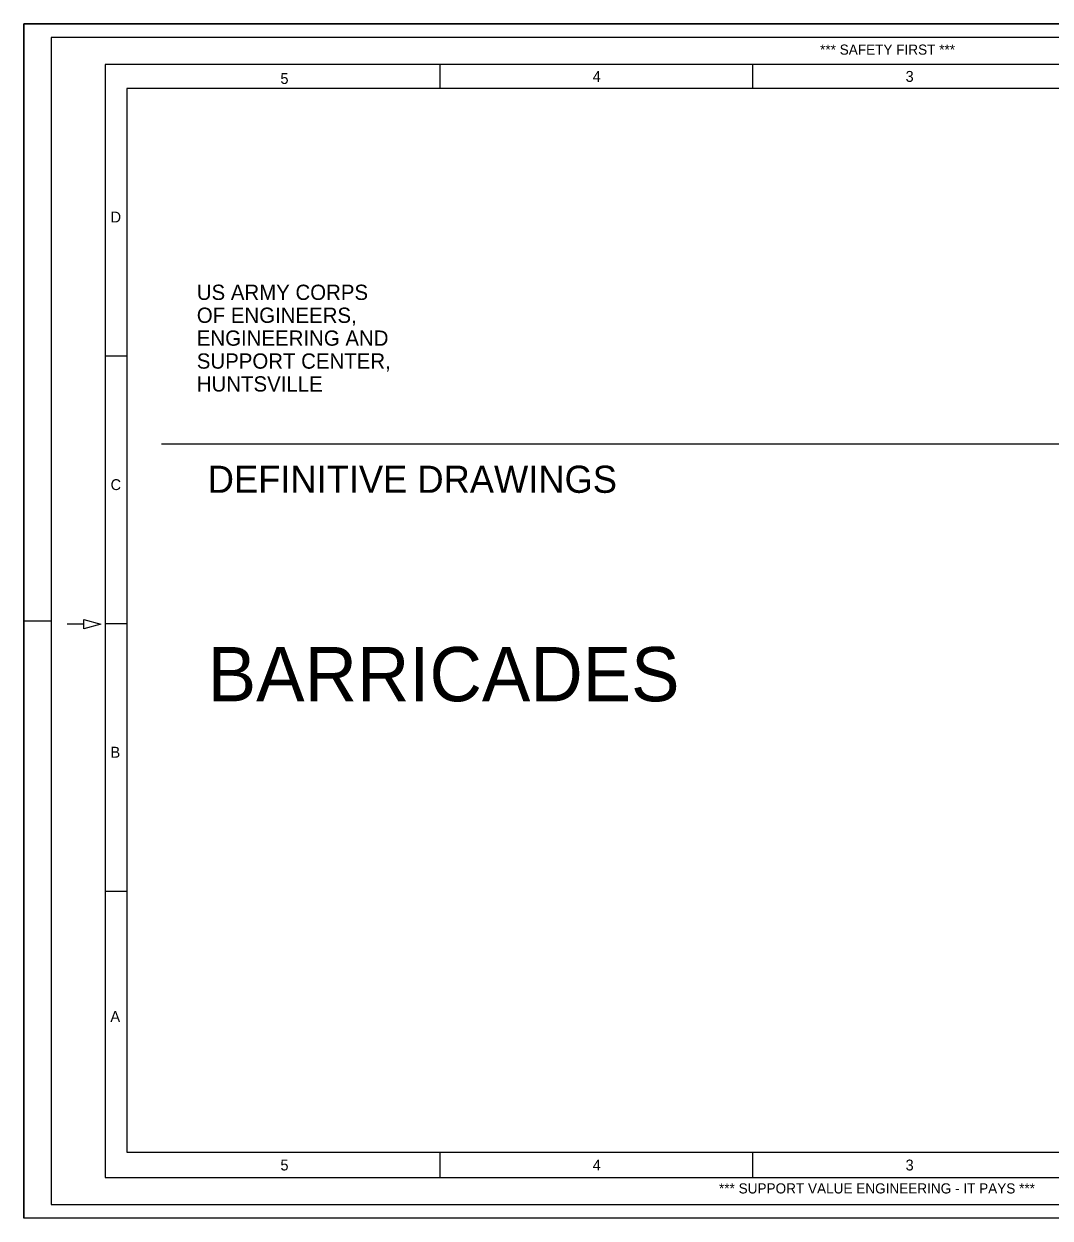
# Model space of a CAD drawing. Extents: x -0.04 to 2.79, y -0.02 to 1.81.
# Drawn here: x -0.042 to 1.534, y -0.021 to 1.813 of the extents above; entities that cross this region are included whole.
import ezdxf

# ---------------------------------------------------------------- set-up
doc = ezdxf.new("R2010")
doc.units = 0
for name, color, linetype in [('G-ANNO-NPLT', 7, 'Continuous'), ('G-ANNO-PLOT', 7, 'Continuous'), ('G-ANNO-TEXT', 7, 'Continuous'), ('G-ANNO-TTLB', 7, 'Continuous'), ('Level 63', 7, 'Continuous')]:
    doc.layers.add(name, color=color, linetype=linetype)

msp = doc.modelspace()

# ---------------------------------------------------------------- linework, layer by layer
at = {"layer": 'G-ANNO-NPLT'}
msp.add_lwpolyline([(-0.0417, 1.8125), (2.7917, 1.8125), (2.7917, -0.0208), (-0.0417, -0.0208)], close=True, dxfattribs=at)
at = {"layer": 'G-ANNO-PLOT'}
for p, q in [((2.7917, 1.8125), (-0.0417, 1.8125)), ((-0.0417, 1.8125), (-0.0417, -0.0208)), ((0, 0.8958), (-0.0417, 0.8958)), ((2.7917, -0.0208), (-0.0417, -0.0208))]:
    msp.add_line(p, q, dxfattribs=at)
msp.add_lwpolyline([(0, 0), (2.7917, 0), (2.7917, 1.7917), (0, 1.7917)], close=True, dxfattribs=at)
at = {"layer": 'G-ANNO-TTLB'}
for p, q in [((0.5978, 1.7131), (0.5978, 1.75)), ((1.0778, 1.7131), (1.0778, 1.75)), ((0.1166, 1.3022), (0.0833, 1.3022)), ((0.0506, 0.891), (0.0246, 0.891)), ((0.1166, 0.8914), (0.0833, 0.8914)), ((0.1166, 0.4806), (0.0833, 0.4806)), ((0.5978, 0.0418), (0.5978, 0.0803)), ((1.0778, 0.0418), (1.0778, 0.0803)), ((0.0833, 0.0417), (0.0833, 0.0417))]:
    msp.add_line(p, q, dxfattribs=at)
for points in [[(0.2515, 1.75), (0.0833, 1.75), (0.0833, 0.0417)], [(0.0833, 0.0417), (2.7292, 0.0417), (2.7292, 1.75), (0.2515, 1.75)], [(0.1166, 0.0803), (2.695, 0.0803), (2.695, 1.7131), (0.1166, 1.7131)], [(0.1166, 1.7131), (0.1166, 0.0803)]]:
    msp.add_lwpolyline(points, dxfattribs=at)
msp.add_lwpolyline([(0.0506, 0.8983), (0.0765, 0.891), (0.0506, 0.8837)], close=True, dxfattribs=at)
at = {"layer": 'Level 63'}
msp.add_line((0.1695, 1.1676), (2.4553, 1.1676), dxfattribs=at)

# ---------------------------------------------------------------- texts
at = {"layer": 'G-ANNO-TEXT'}
for s, height, p in [('US ARMY CORPS', 0.023438, (0.2239, 1.3887)), ('OF ENGINEERS, ', 0.023438, (0.2239, 1.3535)), ('ENGINEERING AND', 0.023438, (0.2239, 1.3184)), ('SUPPORT CENTER,', 0.023438, (0.2239, 1.2832)), ('HUNTSVILLE', 0.02344, (0.2239, 1.2481))]:
    msp.add_text(s, height=height, dxfattribs=at).set_placement(p)
at = {"layer": 'G-ANNO-TTLB'}
for s, height, p in [('*** SAFETY FIRST ***', 0.015583, (1.181, 1.7652)), ('5', 0.0167, (0.3523, 1.7203)), ('4', 0.0167, (0.8319, 1.7235)), ('3', 0.0167, (1.3123, 1.7235)), ('D', 0.0167, (0.0915, 1.5076)), ('C', 0.0167, (0.0915, 1.0968)), ('B', 0.0167, (0.0914, 0.686)), ('A', 0.0167, (0.0912, 0.2804)), ('5', 0.0167, (0.3523, 0.0523)), ('4', 0.0167, (0.8319, 0.0523)), ('3', 0.0167, (1.3123, 0.0523)), ('*** SUPPORT VALUE ENGINEERING - IT PAYS ***', 0.015583, (1.0258, 0.017))]:
    msp.add_text(s, height=height, dxfattribs=at).set_placement(p)
at = {"layer": 'Level 63'}
for s, height, p in [('DEFINITIVE DRAWINGS', 0.041667, (0.2407, 1.0926)), ('BARRICADES', 0.08333, (0.2407, 0.7726))]:
    msp.add_text(s, height=height, dxfattribs=at).set_placement(p)

doc.saveas('drawing.dxf')
